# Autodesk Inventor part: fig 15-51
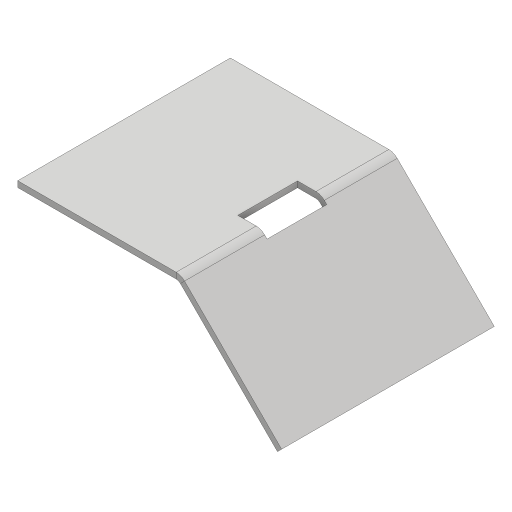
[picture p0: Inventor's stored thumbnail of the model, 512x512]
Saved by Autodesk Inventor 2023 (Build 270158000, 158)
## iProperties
Created: 2015-07
Part Number: fig 15-51
Material: Generic
Document SubType Name: Sheet Metal
Designer: Sandeep
Density: 1 g/cm^3
Sheet Metal Rule: Default_mm
Appearance: Default
Author: Sandeep
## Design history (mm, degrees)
node "Face1"
  sketch "Sketch1"
    geometry: L1 (-9.283, 8.313)-(4.503, 8.313); L2 (4.503, 8.313)-(4.503, -9.63); L3 (4.503, -9.63)-(-9.283, -9.63); L4 (-9.283, -9.63)-(-9.283, 8.313); 1 further point
    constraints: 8 end point, 2 parallel, 1 horizontal, 1 perpendicular
node "Flange1"
sketch "Sketch3"
  geometry: L1 (2.535, 2.162)-(6.789, 2.162); L2 (6.789, 2.162)-(6.789, -2.878); L3 (6.789, -2.878)-(2.535, -2.878); L4 (2.535, -2.878)-(2.535, 2.162); 1 further point
  constraints: 8 end point, 2 parallel, 1 horizontal, 1 perpendicular
cut "Cut1" sketch "Sketch3" dims "d11" = 0.5 (= Thickness), "d12" = 0
body "Solid1"
face "Plate1" dims "d13" = 0.5 (= Thickness)
sketch "Sketch2"
  geometry: L1 (0, -12)-(17.943, -12); L2 (17.943, -12)-(17.943, 0); 1 other entity
  constraints: 4 end point, 4 other
face "Plate2" dims "d1" = 0.5 (= BendReliefWidth), "d2" = 0.25 (= BendReliefDepth), "d3" = 1 (= MinimumRemnant), "d4" = 0.5 (= BendRadius), "d5" = 12, "d6" = 45 deg, "d7" = 0.5 (= BendRadius), "d8" = 2 (= CornerReliefSize), "d9" = 0.5 (= GapSize), "d10" = 0.5 (= JacobiRadiusSize), "d13" = 0.5 (= Thickness), "SeamGap" = 0.01
bend "Bend1" dims "d1" = 0.5 (= BendReliefWidth), "d2" = 0.25 (= BendReliefDepth), "d3" = 1 (= MinimumRemnant), "d4" = 0.5 (= BendRadius), "d5" = 12, "d6" = 45 deg, "d7" = 0.5 (= BendRadius), "d13" = 0.5 (= Thickness), "SeamGap" = 0.01
feature "Corner1" dims "d5" = 12, "d6" = 45 deg, "d8" = 2 (= CornerReliefSize), "d9" = 0.5 (= GapSize), "d10" = 0.5 (= JacobiRadiusSize)
other parameters: "Thickness" = 0.5, "BendRadius" = 0.5 (= Thickness), "BendReliefWidth" = 0.5 (= Thickness), "BendReliefDepth" = 0.25 (= 0.5 x Thickness), "CornerReliefSize" = 2 (= 4 x Thickness), "MinimumRemnant" = 1 (= 2 x Thickness), "TransitionRadius" = 0.5 (= BendRadius), "JacobiRadiusSize" = 0.5 (= BendRadius), "GapSize" = 0.5 (= Thickness), "d0" = 0.5 (= BendRadius)
